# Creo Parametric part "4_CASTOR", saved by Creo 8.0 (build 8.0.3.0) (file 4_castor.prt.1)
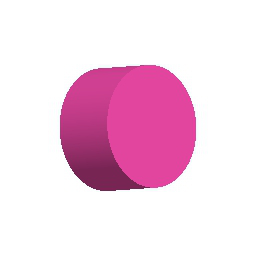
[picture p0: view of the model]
Units: millimeter Newton Second (mmNs); MM, TONNE, SECS

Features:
  1. datum plane "DTM1"
  2. protrusion

Layers: 0_ALL_AXIS, 0_ALL_CSYS, 0_ALL_CURVES, 0_ALL_PLANES, 0_ALL_POINTS, 0_ALL_SURFS, CASTOR

Surfaces: 2 plane, 1 cylinder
